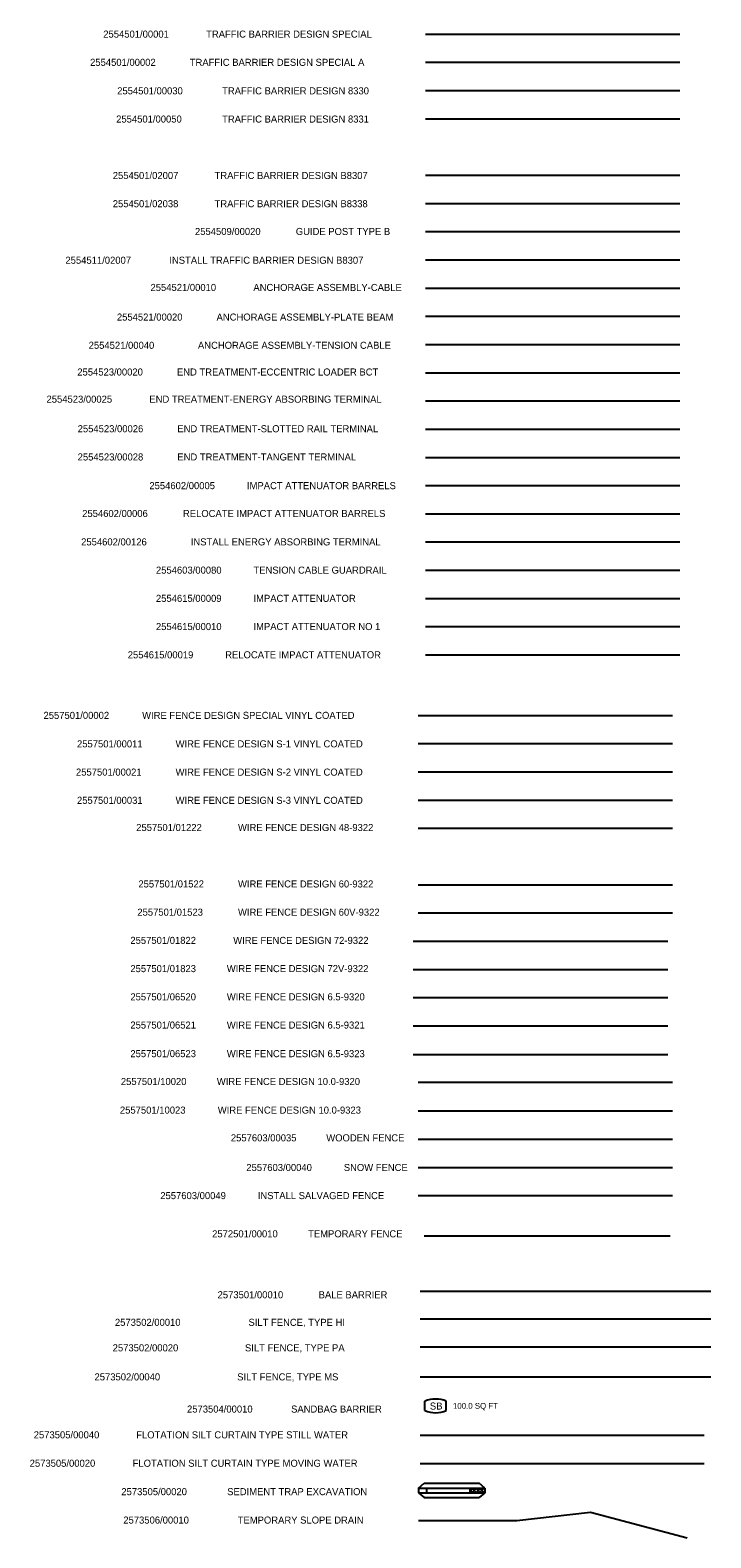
# Model space of a CAD drawing. Extents: x 2147716 to 2176321, y 2125040 to 2131750.
# Drawn here: x 2155051 to 2155775, y 2127874 to 2129477 of the extents above; entities that cross this region are included whole.
import ezdxf

# ---------------------------------------------------------------- set-up
doc = ezdxf.new("R2010")
doc.units = 0
for name, color, linetype in [('DETAIL TXT', 7, 'Continuous'), ('ERSN CTRL', 7, 'Continuous'), ('FENCE', 7, 'Continuous'), ('GDRL', 7, 'Continuous')]:
    doc.layers.add(name, color=color, linetype=linetype)

msp = doc.modelspace()

# ---------------------------------------------------------------- linework, layer by layer
at = {"layer": 'ERSN CTRL'}
for p, q in [((2155465.7, 2128136.4), (2155774.6, 2128136.4)), ((2155465.7, 2128107.2), (2155774.6, 2128107.2)), ((2155465.7, 2128077.3), (2155774.6, 2128077.3)), ((2155465.7, 2128045.6), (2155774.6, 2128045.6)), ((2155470.8, 2128014.7), (2155470.8, 2128019.7)), ((2155470.8, 2128009.7), (2155470.8, 2128014.7)), ((2155493.4, 2128014.7), (2155493.4, 2128019.7)), ((2155493.4, 2128009.7), (2155493.4, 2128014.7)), ((2155465.6, 2127983.5), (2155767.3, 2127983.5)), ((2155465.6, 2127953.4), (2155767.3, 2127953.4)), ((2155463.9, 2127927.3), (2155469.8, 2127932.3)), ((2155463.9, 2127927.3), (2155463.9, 2127922.3)), ((2155463.9, 2127927.3), (2155481.2, 2127927.3)), ((2155469.8, 2127932.3), (2155481.2, 2127932.3)), ((2155472.4, 2127927.3), (2155472.4, 2127922.3)), ((2155481.2, 2127932.3), (2155528.5, 2127932.3)), ((2155481.2, 2127927.3), (2155534.4, 2127927.3)), ((2155518.4, 2127927.3), (2155518.4, 2127922.3)), ((2155518.4, 2127924), (2155521.7, 2127927.3)), ((2155520.7, 2127927.3), (2155525.7, 2127922.3)), ((2155520.7, 2127922.3), (2155525.7, 2127927.3)), ((2155524.7, 2127927.3), (2155529.7, 2127922.3)), ((2155524.7, 2127922.3), (2155529.7, 2127927.3)), ((2155534.4, 2127927.3), (2155528.5, 2127932.3)), ((2155528.7, 2127927.3), (2155533.7, 2127922.3)), ((2155528.7, 2127922.3), (2155533.7, 2127927.3)), ((2155532.7, 2127927.3), (2155534.4, 2127925.6)), ((2155534.4, 2127927.3), (2155534.4, 2127922.3)), ((2155463.9, 2127922.3), (2155469.9, 2127917.3)), ((2155463.9, 2127922.3), (2155481.2, 2127922.3)), ((2155469.9, 2127917.3), (2155481.2, 2127917.3)), ((2155481.2, 2127922.3), (2155534.4, 2127922.3)), ((2155481.2, 2127917.3), (2155528.4, 2127917.3)), ((2155518.4, 2127925.6), (2155521.7, 2127922.3)), ((2155534.4, 2127922.3), (2155528.4, 2127917.3)), ((2155532.7, 2127922.3), (2155534.4, 2127924)), ((2155568.3, 2127892.9), (2155646.8, 2127901.8)), ((2155646.8, 2127901.8), (2155749.5, 2127874.3)), ((2155464, 2127892.9), (2155568.3, 2127892.9))]:
    msp.add_line(p, q, dxfattribs=at)
for centre, start, end in [((2155482.1, 2127992.4), 67.4378, 112.5622), ((2155482.1, 2128036.8), 247.4378, 292.5622)]:
    msp.add_arc(centre, 29.5, start, end, dxfattribs=at)
at = {"layer": 'FENCE'}
for p, q in [((2155463.4, 2128748.6), (2155733.8, 2128748.6)), ((2155463.4, 2128718.6), (2155733.8, 2128718.6)), ((2155463.4, 2128688.6), (2155733.8, 2128688.6)), ((2155463.4, 2128658.6), (2155733.8, 2128658.6)), ((2155463.4, 2128628.6), (2155733.8, 2128628.6)), ((2155463.4, 2128568.6), (2155733.8, 2128568.6)), ((2155463.4, 2128538.6), (2155733.8, 2128538.6)), ((2155458.3, 2128508.6), (2155728.7, 2128508.6)), ((2155458.3, 2128478.6), (2155728.7, 2128478.6)), ((2155458.3, 2128448.6), (2155728.7, 2128448.6)), ((2155458.3, 2128418.6), (2155728.7, 2128418.6)), ((2155458.3, 2128388.2), (2155728.7, 2128388.2)), ((2155463.4, 2128358.6), (2155733.8, 2128358.6)), ((2155463.4, 2128328.2), (2155733.8, 2128328.2)), ((2155463.4, 2128298.2), (2155733.8, 2128298.2)), ((2155463.4, 2128268.2), (2155733.8, 2128268.2)), ((2155463.4, 2128238.2), (2155733.8, 2128238.2)), ((2155469.9, 2128195.4), (2155731.3, 2128195.4))]:
    msp.add_line(p, q, dxfattribs=at)
at = {"layer": 'GDRL'}
for p, q in [((2155471.2, 2129472.9), (2155741.6, 2129472.9)), ((2155471.2, 2129442.9), (2155741.6, 2129442.9)), ((2155471.2, 2129412.9), (2155741.6, 2129412.9)), ((2155471.2, 2129382.9), (2155741.6, 2129382.9)), ((2155471.2, 2129322.9), (2155741.6, 2129322.9)), ((2155471.2, 2129292.9), (2155741.6, 2129292.9)), ((2155471.2, 2129262.9), (2155741.6, 2129262.9)), ((2155471.2, 2129232.9), (2155741.6, 2129232.9)), ((2155471.2, 2129202.9), (2155741.6, 2129202.9)), ((2155471.2, 2129172.9), (2155741.6, 2129172.9)), ((2155471.2, 2129142.9), (2155741.6, 2129142.9)), ((2155471.2, 2129112.9), (2155741.6, 2129112.9)), ((2155471.2, 2129082.9), (2155741.6, 2129082.9)), ((2155471.2, 2129052.9), (2155741.6, 2129052.9)), ((2155471.2, 2129022.9), (2155741.6, 2129022.9)), ((2155471.2, 2128992.9), (2155741.6, 2128992.9)), ((2155471.2, 2128962.9), (2155741.6, 2128962.9)), ((2155471.2, 2128933), (2155741.6, 2128933)), ((2155471.2, 2128903), (2155741.6, 2128903)), ((2155471.2, 2128873), (2155741.6, 2128873)), ((2155471.2, 2128843), (2155741.6, 2128843)), ((2155471.2, 2128813), (2155741.6, 2128813))]:
    msp.add_line(p, q, dxfattribs=at)

# ---------------------------------------------------------------- texts
at = {"layer": 'DETAIL TXT'}
for s, p in [('2554501/00001', (2155128.9, 2129469.1)), ('TRAFFIC BARRIER DESIGN SPECIAL', (2155238.2, 2129469.1)), ('2554501/00002', (2155114.9, 2129439.1)), ('TRAFFIC BARRIER DESIGN SPECIAL A', (2155220.8, 2129439.1)), ('2554501/00030', (2155143.7, 2129408.8)), ('TRAFFIC BARRIER DESIGN 8330', (2155255.2, 2129408.8)), ('2554501/00050', (2155142.6, 2129378.8)), ('TRAFFIC BARRIER DESIGN 8331', (2155255.2, 2129378.8)), ('2554501/02007', (2155139, 2129318.8)), ('TRAFFIC BARRIER DESIGN B8307', (2155247.2, 2129318.8)), ('2554501/02038', (2155139, 2129288.8)), ('TRAFFIC BARRIER DESIGN B8338', (2155247.2, 2129288.8)), ('2554509/00020', (2155226.4, 2129259.3)), ('GUIDE POST TYPE B', (2155333.5, 2129259.3)), ('2554511/02007', (2155088.7, 2129228.7)), ('INSTALL TRAFFIC BARRIER DESIGN B8307', (2155199.1, 2129228.7)), ('2554521/00010', (2155179.1, 2129199.8)), ('ANCHORAGE ASSEMBLY-CABLE', (2155288.4, 2129199.8)), ('2554521/00020', (2155143.4, 2129168.3)), ('ANCHORAGE ASSEMBLY-PLATE BEAM', (2155249.3, 2129168.3)), ('2554521/00040', (2155113.4, 2129138.3)), ('ANCHORAGE ASSEMBLY-TENSION CABLE', (2155229.5, 2129138.3)), ('2554523/00020', (2155101.3, 2129109.9)), ('END TREATMENT-ECCENTRIC LOADER BCT', (2155207.2, 2129109.9)), ('2554523/00025', (2155068.6, 2129081)), ('END TREATMENT-ENERGY ABSORBING TERMINAL', (2155177.9, 2129081)), ('2554523/00026', (2155101.7, 2129049.6)), ('END TREATMENT-SLOTTED RAIL TERMINAL', (2155207.6, 2129049.6)), ('2554523/00028', (2155101.7, 2129019.6)), ('END TREATMENT-TANGENT TERMINAL', (2155207.6, 2129019.6)), ('2554602/00005', (2155177.9, 2128989.1)), ('IMPACT ATTENUATOR BARRELS', (2155281.6, 2128989.1)), ('2554602/00006', (2155106.5, 2128959.5)), ('RELOCATE IMPACT ATTENUATOR BARRELS', (2155213.6, 2128959.5)), ('2554602/00126', (2155105.4, 2128929.3)), ('INSTALL ENERGY ABSORBING TERMINAL', (2155221.9, 2128929.3)), ('2554603/00080', (2155184.9, 2128899.3)), ('TENSION CABLE GUARDRAIL', (2155288.5, 2128899.3)), ('2554615/00009', (2155184.9, 2128869.3)), ('IMPACT ATTENUATOR', (2155288.5, 2128869.3)), ('2554615/00010', (2155184.9, 2128839.3)), ('IMPACT ATTENUATOR NO 1', (2155288.5, 2128839.3)), ('2554615/00019', (2155154.9, 2128809.3)), ('RELOCATE IMPACT ATTENUATOR', (2155258.5, 2128809.3)), ('2557501/00002', (2155065.4, 2128744.9)), ('WIRE FENCE DESIGN SPECIAL VINYL COATED', (2155170.2, 2128744.9)), ('2557501/00011', (2155101, 2128714.6)), ('WIRE FENCE DESIGN S-1 VINYL COATED', (2155205.8, 2128714.6)), ('2557501/00021', (2155099.9, 2128684.6)), ('WIRE FENCE DESIGN S-2 VINYL COATED', (2155205.8, 2128684.6)), ('2557501/00031', (2155101, 2128654.6)), ('WIRE FENCE DESIGN S-3 VINYL COATED', (2155205.8, 2128654.6)), ('2557501/01222', (2155163.9, 2128625.7)), ('WIRE FENCE DESIGN 48-9322', (2155272.1, 2128625.7)), ('2557501/01522', (2155166.2, 2128565.7)), ('WIRE FENCE DESIGN 60-9322', (2155272.1, 2128565.7)), ('2557501/01523', (2155165.1, 2128535.7)), ('WIRE FENCE DESIGN 60V-9322', (2155272.1, 2128535.7)), ('2557501/01822', (2155157.7, 2128505.7)), ('WIRE FENCE DESIGN 72-9322', (2155267, 2128505.7)), ('2557501/01823', (2155157.7, 2128475.7)), ('WIRE FENCE DESIGN 72V-9322', (2155260.2, 2128475.7)), ('2557501/06520', (2155157.7, 2128445.7)), ('WIRE FENCE DESIGN 6.5-9320', (2155260.2, 2128445.7)), ('2557501/06521', (2155157.7, 2128415.7)), ('WIRE FENCE DESIGN 6.5-9321', (2155260.2, 2128415.7)), ('2557501/06523', (2155157.7, 2128385.3)), ('WIRE FENCE DESIGN 6.5-9323', (2155260.2, 2128385.3)), ('2557501/10020', (2155147.6, 2128355.7)), ('WIRE FENCE DESIGN 10.0-9320', (2155249.6, 2128355.7)), ('2557501/10023', (2155146.6, 2128325.3)), ('WIRE FENCE DESIGN 10.0-9323', (2155250.6, 2128325.3)), ('2557603/00035', (2155264.5, 2128295.8)), ('WOODEN FENCE', (2155365.9, 2128295.8)), ('2557603/00040', (2155280.9, 2128264.3)), ('SNOW FENCE', (2155384.5, 2128264.3)), ('2557603/00049', (2155189.5, 2128234.4)), ('INSTALL SALVAGED FENCE', (2155293.1, 2128234.4)), ('2572501/00010', (2155244.6, 2128193.8)), ('TEMPORARY FENCE', (2155346.6, 2128193.8)), ('2573501/00010', (2155250.4, 2128129)), ('BALE BARRIER', (2155357.8, 2128129)), ('2573502/00010', (2155141.3, 2128099.7)), ('SILT FENCE, TYPE HI', (2155283.2, 2128099.7)), ('2573502/00020', (2155138.9, 2128072.6)), ('SILT FENCE, TYPE PA', (2155279.5, 2128072.6)), ('2573502/00040', (2155119.6, 2128041.7)), ('SILT FENCE, TYPE MS', (2155271.2, 2128041.7)), ('2573504/00010', (2155217.9, 2128007.5)), ('SANDBAG BARRIER', (2155328.5, 2128007.5)), ('2573505/00040', (2155055, 2127980.1)), ('FLOTATION SILT CURTAIN TYPE STILL WATER', (2155163.9, 2127980.1)), ('2573505/00020', (2155050.7, 2127949.9)), ('FLOTATION SILT CURTAIN TYPE MOVING WATER', (2155160.1, 2127949.9)), ('2573505/00020', (2155148.1, 2127919.7)), ('SEDIMENT TRAP EXCAVATION', (2155260.6, 2127919.7)), ('2573506/00010', (2155150.2, 2127889.5)), ('TEMPORARY SLOPE DRAIN', (2155271.8, 2127889.5))]:
    msp.add_text(s, height=7.5, dxfattribs=at).set_placement(p)
at = {"layer": 'ERSN CTRL'}
for s, height, p in [('SB', 7.5, (2155476, 2128010.7)), ('100.0 SQ FT', 6.25, (2155500.5, 2128011.5))]:
    msp.add_text(s, height=height, dxfattribs=at).set_placement(p)

doc.saveas('drawing.dxf')
